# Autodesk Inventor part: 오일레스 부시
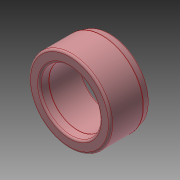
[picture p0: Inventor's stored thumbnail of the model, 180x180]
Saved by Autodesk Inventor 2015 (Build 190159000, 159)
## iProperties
Created: 2023-11
Part Number: 오일레스 부시
Material: 강철, 합금
Document SubType Name: Modeling
Designer: mdu-01
Density: 1 g/cm^3
Appearance: 기본값(1)
Author: mdu-01
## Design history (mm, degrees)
sketch "스케치1"
  geometry: L1 (7.772, 0)-(9.5, 0); L2 (10, -0.5)-(10, -7.934); L3 (9.08, -10)-(7.5, -10); L4 (7, -9.5)-(7, -2.044); L5 (0, 0)-(0, -10); L6 (9.983, -8.064)-(9.563, -9.629); L7 (7.008, -1.957)-(7.28, -0.413); A1 r 0.5 centre (9.5, -0.5) between (10, -0.5) and (9.5, 0); A2 r 0.5 centre (7.5, -9.5) between (7, -9.5) and (7.5, -10); A3 r 0.5 centre (9.08, -9.5) between (9.08, -10) and (9.563, -9.629); A4 r 0.5 centre (7.772, -0.5) between (7.772, 0) and (7.28, -0.413); A5 r 0.5 centre (7.5, -2.044) between (7.008, -1.957) and (7, -2.044); A6 r 0.5 centre (9.5, -7.934) between (9.983, -8.064) and (10, -7.934); 4 further points
  constraints: 14 end point, 12 point on circle, 12 tangent, 10 point on line, 6 centre point, 4 equal radius, 3 parallel, 1 horizontal, 1 perpendicular
  dimensions: "d0" = 10 distance of L5.start L5.end; "d1" = 14 diameter of L4 L5; "d2" = 20 diameter of L2 L5; "d3" = 0.5 radius of A1; "d4" = 2 distance of point (10, -8) point (10, -10); "d5" = 15 deg angle of L2 L6; "d6" = 2 distance of point (7, -2) point (7, 0); "d7" = 10 deg angle of L4 L7; "d8" = 0.5 radius of A3
revolve "회전1" sketch "스케치1" stored, may be unused: angle "d9" = 90 deg
node "솔리드1"
